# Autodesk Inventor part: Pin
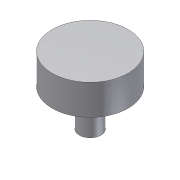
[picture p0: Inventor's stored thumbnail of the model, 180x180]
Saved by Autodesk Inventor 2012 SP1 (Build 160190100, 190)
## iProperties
Created: 2006-09
Part Number: Pin
Document SubType Name: Modeling
Mass: 1.85059 g
Surface Area: 9.99419 cm^2
Volume: 1.85059 cm^3
Density: 1 g/cm^3
Material: Default
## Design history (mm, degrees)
sketch "Sketch1"
  geometry: C1 r 2.5 at (0, 0); 1 further point
  constraints: 1 centre point, 1 coincident
  dimensions: "d0" = 5 diameter of C1
extrude "Extrusion1" new body sketch "Sketch1" distance "d1" = 12; taper "d2" = 0 deg
sketch "Sketch2"
  geometry: C1 r 8.75 at (0, 0); 1 further point
  constraints: 1 centre point, 1 coincident
  dimensions: "d3" = 17.5 diameter of C1
extrude "Extrusion2" join sketch "Sketch2" stored distance "d4" = 7; taper "d5" = 0 deg
body "Solid1"
